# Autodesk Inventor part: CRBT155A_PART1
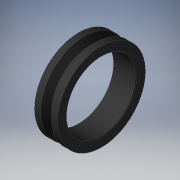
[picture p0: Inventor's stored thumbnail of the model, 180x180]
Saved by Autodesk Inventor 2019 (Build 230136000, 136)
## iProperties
Created: 2023-09
Part Number: CRBT155A_PART1
Material: Generic
Catalog Web Link: www.cadenas.de
Description: -
Vendor: IKO
Document SubType Name: Modeling
Designer: psAdmin
Manufacturer: IKO
Mass: 0.470551 g
Surface Area: 7.95035 cm^2
Volume: 0.470551 cm^3
Density: 1 g/cm^3
Appearance: PSOLRGB-175-175-175
Category: PARTsolutions
Company: IKO
Title: CRBT155A_PART1
Author: Cadenas PARTsolutions
PSOL_IDENT_0: {$CADENAS_DATA/23d-libs/iko/iko_bearings/crossed_rb/ultra_slim_type_crb/ultra_slim_type_crbt.prj},23
PSOL_IDENT_1: 2 {VTYP=3D},{NB=CRBT155A_PART1},{LINA=CRBT155A_PART1},{NN=Ultra Slim Type Crossed Roller Bearings (C
PSOL_IDENT_2: RBT...A)_PART1},{NOPRJ=TRUE},{DATE=09.07.2020 23:28:49},{GEOMDATE=08.07.2020 06:24:28},{VERSION=},{L
PSOL_IDENT_3: INEID=220},{WBVAR=},{WBNUMERIC=}  {NB=CRBT155A_PART1},{LINA=CRBT155A_PART1},{KT=DUMMY},{IDNR=},{STDR
PSOL_IDENT_4: T=15},{ORDER=CRBT155A},{MASS=11.9},{SD=15},{D=26},{B=5},{SR=0.15},{SDA=17.5},{DA=22.0},{DAR=2.0},{ZE
PSOL_IDENT_5: FF=16},{RS=0.3},{DETC=1.6},{PCDRL=19.6},{SDOR=20.10},{DIRR=19.10},{COG=0.0},{SDOG=0.0},{OH=0.0},{NH=
PSOL_IDENT_6: 0},{CR=1320},{COR=1110},{SC=0},{N=8},{N1=1.67}
NB: CRBT155A_PART1
NBSYN: $ORDER._PART1
LINA: CRBT155A_PART1
CATALOG: IKO (Nippon Thompson
STDRT: 15
ORDER: CRBT155A
MASS: 11.9
SD: 15
D: 26
B: 5
SR: 0.15
SDA: 17.5
DA: 22
CR: 1320
COR: 1110
SUPPLIER: IKO
ARTICLENO: CRBT155A_PART1
BOMINFO: CRBT155A_PART1
CREATOR: CADENAS GmbH
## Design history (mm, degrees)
sketch "Sketch_1"
  geometry: L1 (5, 0)-(0, 0); L2 (0.15, 7.5)-(4.85, 7.5); L3 (5, 7.65)-(5, 9.55); L4 (5, 9.55)-(0, 9.55); L5 (0, 9.55)-(0, 7.65); A1 r 0.15 centre (0.15, 7.65) between (0, 7.65) and (0.15, 7.5); A2 r 0.15 centre (4.85, 7.65) between (4.85, 7.5) and (5, 7.65)
  constraints: 10 end point, 4 point on circle, 2 centre point
revolve "Revolution1" sketch "Sketch_1" stored, may be unused: angle "d0" = 360 deg
sketch "Sketch_2"
  geometry: L1 (3.5, 0)-(1.5, 0); L2 (1.086, 9.8)-(2.5, 8.386); L3 (2.5, 8.386)-(3.914, 9.8); L4 (3.914, 9.8)-(2.5, 11.214); L5 (2.5, 11.214)-(1.086, 9.8)
  constraints: 10 end point
revolve "Revolution2" sketch "Sketch_2" stored, may be unused: angle "d1" = 360 deg
body "Solid1"
